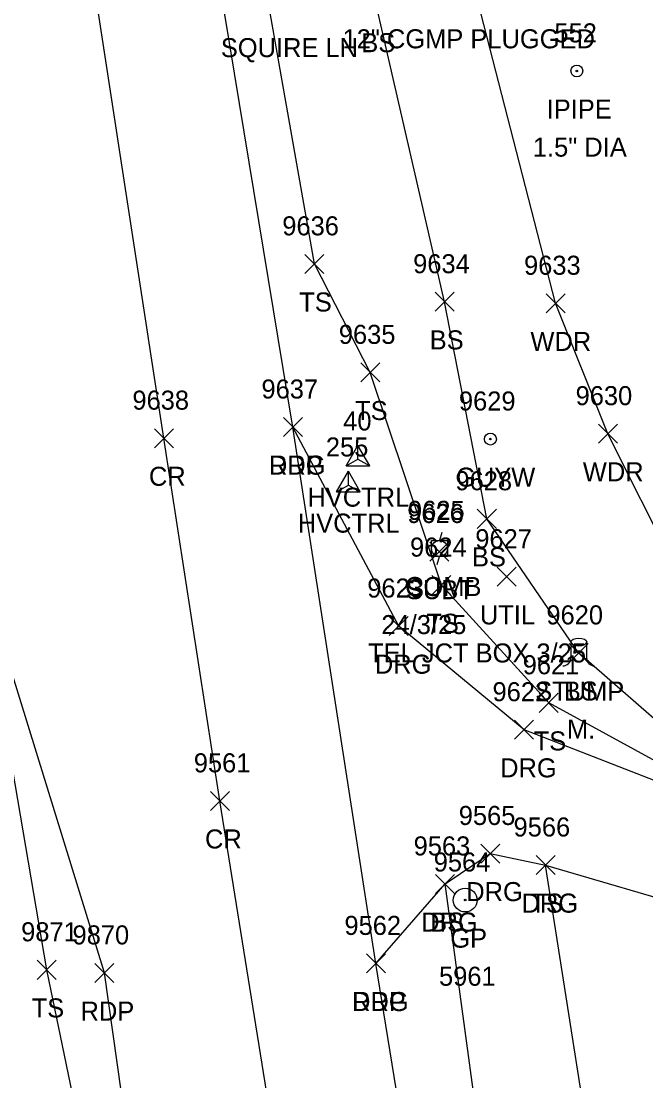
# Model space of a CAD drawing. Extents: x 1439173 to 1457902, y 641926 to 659889.
# Drawn here: x 1448206.5 to 1448272.1, y 646731.6 to 646843 of the extents above; entities that cross this region are included whole.
import ezdxf

# ---------------------------------------------------------------- set-up
doc = ezdxf.new("R2010")
doc.units = 0
for name, color, linetype in [('C_A', 7, 'Continuous'), ('C_I', 7, 'Continuous'), ('CPSM', 7, 'Continuous'), ('D_C', 7, 'Continuous'), ('L_A', 7, 'Continuous'), ('L_C', 7, 'Continuous'), ('L_I', 7, 'Continuous'), ('L_TIC', 7, 'Continuous'), ('LAWA', 7, 'Continuous'), ('LELB', 7, 'Continuous'), ('LTS', 7, 'Continuous'), ('M_A', 7, 'Continuous'), ('M_C', 7, 'Continuous'), ('M_I', 7, 'Continuous'), ('MPIP', 7, 'Continuous'), ('P_A', 7, 'Continuous'), ('P_I', 7, 'Continuous'), ('P_TIC', 7, 'Continuous'), ('PET', 7, 'Continuous'), ('PRC', 7, 'Continuous'), ('R_A', 7, 'Continuous'), ('R_C', 7, 'Continuous'), ('R_I', 7, 'Continuous'), ('R_TIC', 7, 'Continuous'), ('RDG', 7, 'Continuous'), ('RGP', 7, 'Continuous'), ('S_C', 7, 'Continuous'), ('U_A', 7, 'Continuous'), ('U_C', 7, 'Continuous'), ('U_I', 7, 'Continuous'), ('U_TIC', 7, 'Continuous'), ('UDEFAULT', 7, 'Continuous'), ('UP', 7, 'Continuous'), ('UPGW', 7, 'Continuous')]:
    doc.layers.add(name, color=color, linetype=linetype)

msp = doc.modelspace()

# ---------------------------------------------------------------- linework, layer by layer
at = {"layer": 'CPSM'}
for p, q in [((1448240.62, 646796.24), (1448241.87, 646798.4)), ((1448243.12, 646796.24), (1448241.87, 646798.4)), ((1448241.87, 646796.96), (1448241.87, 646798.4)), ((1448240.62, 646796.24), (1448241.87, 646796.96)), ((1448241.87, 646796.96), (1448241.87, 646796.96)), ((1448241.87, 646796.96), (1448243.12, 646796.24)), ((1448239.61, 646793.51), (1448240.86, 646795.67)), ((1448240.62, 646796.24), (1448243.12, 646796.24)), ((1448242.11, 646793.51), (1448240.86, 646795.67)), ((1448240.86, 646794.23), (1448240.86, 646795.67)), ((1448239.61, 646793.51), (1448240.86, 646794.23)), ((1448240.86, 646794.23), (1448240.86, 646794.23)), ((1448240.86, 646794.23), (1448242.11, 646793.51)), ((1448239.61, 646793.51), (1448242.11, 646793.51))]:
    msp.add_line(p, q, dxfattribs=at)
at = {"layer": 'L_TIC'}
for points in [[(1448236.29, 646816.46), (1448238.29, 646818.46)], [(1448238.29, 646816.46), (1448236.29, 646818.46)], [(1448249.97, 646812.48), (1448251.97, 646814.48)], [(1448251.97, 646812.48), (1448249.97, 646814.48)], [(1448261.63, 646812.32), (1448263.63, 646814.32)], [(1448263.63, 646812.32), (1448261.63, 646814.32)], [(1448242.16, 646805.06), (1448244.16, 646807.06)], [(1448244.16, 646805.06), (1448242.16, 646807.06)], [(1448267.14, 646798.62), (1448269.14, 646800.62)], [(1448269.14, 646798.62), (1448267.14, 646800.62)], [(1448254.41, 646789.68), (1448256.41, 646791.68)], [(1448256.41, 646789.68), (1448254.41, 646791.68)], [(1448249.64, 646782.71), (1448251.64, 646784.71)], [(1448251.64, 646782.71), (1448249.64, 646784.71)], [(1448264.06, 646775.59), (1448266.06, 646777.59)], [(1448266.06, 646775.59), (1448264.06, 646777.59)], [(1448260.92, 646770.35), (1448262.92, 646772.35)], [(1448262.92, 646770.35), (1448260.92, 646772.35)], [(1448260.58, 646753.31), (1448262.58, 646755.31)], [(1448262.58, 646753.31), (1448260.58, 646755.31)], [(1448250.02, 646751.32), (1448252.02, 646753.32)], [(1448252.02, 646751.32), (1448250.02, 646753.32)], [(1448208.17, 646742.3), (1448210.17, 646744.3)], [(1448210.17, 646742.3), (1448208.17, 646744.3)]]:
    msp.add_lwpolyline(points, dxfattribs=at)
at = {"layer": 'LAWA'}
msp.add_lwpolyline([(1448339.89, 646844.92), (1448320.73, 646824.25), (1448303.84, 646805.93), (1448275.1, 646785.75), (1448268.14, 646799.62), (1448262.63, 646813.32), (1448252.89, 646851.23), (1448275.91, 646859.54), (1448302.67, 646865.98), (1448312.29, 646860.75), (1448323.5, 646861.84), (1448339.6, 646861.16)], dxfattribs=at)
at = {"layer": 'LELB'}
for points in [[(1448221.02, 646679.97), (1448216.65, 646707.27), (1448209.17, 646743.3), (1448202.24, 646783.83), (1448197.14, 646815.73), (1448192.88, 646849.23), (1448188.79, 646883.91), (1448185.57, 646916.7), (1448180.61, 646928.95), (1448176.05, 646935.8), (1448168.91, 646942.17), (1448163.03, 646939.76)], [(1448286.4, 646757.98), (1448261.92, 646771.35), (1448250.64, 646783.71), (1448243.16, 646806.06), (1448237.29, 646817.46), (1448231.43, 646850.8), (1448233.55, 646856.11)], [(1448286.4, 646757.98), (1448265.06, 646776.59), (1448255.41, 646790.68), (1448250.97, 646813.48), (1448243.78, 646844.7), (1448246.32, 646850.31), (1448252.89, 646851.23)], [(1448318.74, 646292.21), (1448316.52, 646298.57), (1448314.96, 646309.84), (1448311.96, 646334.67), (1448308.77, 646355.56), (1448304.36, 646383.09), (1448300.44, 646410.91), (1448294.85, 646448.68), (1448293.89, 646457.32), (1448293.83, 646460.88), (1448290.31, 646478.07), (1448284.75, 646509.86), (1448279.41, 646543.51), (1448274.67, 646580.58), (1448274.88, 646608.07), (1448272.28, 646641.3), (1448269.27, 646674.15), (1448268, 646713.45), (1448261.58, 646754.31)], [(1448301.58, 646507.94), (1448301.83, 646505.93), (1448300.84, 646506.04), (1448298.73, 646516.23), (1448300.58, 646516.66), (1448296.94, 646526.82), (1448285.25, 646550.8), (1448284.84, 646572.85), (1448274.67, 646580.58), (1448269.38, 646609.39), (1448264.85, 646639.41), (1448260.53, 646672.32), (1448256.24, 646713.95), (1448251.02, 646752.32)]]:
    msp.add_lwpolyline(points, dxfattribs=at)
at = {"layer": 'LTS'}
for p, q in [((1448264.23, 646777.73), (1448264.23, 646776.07)), ((1448265.9, 646777.57), (1448265.9, 646777.73)), ((1448265.9, 646777.73), (1448265.9, 646776.07)), ((1448265.07, 646776.59), (1448265.07, 646776.59)), ((1448265.07, 646776.59), (1448265.07, 646776.59)), ((1448265.07, 646776.57), (1448265.07, 646776.57))]:
    msp.add_line(p, q, dxfattribs=at)
msp.add_circle((1448265.07, 646776.59), 0.0833, dxfattribs=at)
for centre, start, end in [((1448263.4, 646776.07), 270, 360), ((1448266.73, 646776.07), 180, 270)]:
    msp.add_arc(centre, 0.833, start, end, dxfattribs=at)
msp.add_ellipse((1448265.07, 646777.73), major_axis=(-0.833, 0), ratio=0.5, dxfattribs=at)
at = {"layer": 'MPIP'}
for radius in [0.625, 0.0833]:
    msp.add_circle((1448264.87, 646837.73), radius, dxfattribs=at)
at = {"layer": 'P_TIC'}
for points in [[(1448234.04, 646799.32), (1448236.04, 646801.32)], [(1448236.04, 646799.32), (1448234.04, 646801.32)], [(1448220.48, 646798.15), (1448222.48, 646800.15)], [(1448222.48, 646798.15), (1448220.48, 646800.15)], [(1448226.36, 646760.05), (1448228.36, 646762.05)], [(1448228.36, 646760.05), (1448226.36, 646762.05)], [(1448242.76, 646742.97), (1448244.76, 646744.97)], [(1448244.76, 646742.97), (1448242.76, 646744.97)], [(1448214.23, 646741.97), (1448216.23, 646743.97)], [(1448216.23, 646741.97), (1448214.23, 646743.97)]]:
    msp.add_lwpolyline(points, dxfattribs=at)
at = {"layer": 'PET'}
for points in [[(1448246.46, 646550.34), (1448240.19, 646586.21), (1448237.44, 646603.85), (1448232.82, 646631.59), (1448226.85, 646667.5), (1448220.22, 646707.78), (1448215.23, 646742.97), (1448202.82, 646783.14), (1448203.37, 646818.93), (1448198.76, 646850.24), (1448193.44, 646884.14), (1448187.94, 646917.18), (1448185.3, 646933.85), (1448181.56, 646957.89), (1448177.35, 646983.4)], [(1448276.96, 646543.22), (1448270.54, 646579.93), (1448265.59, 646610.13), (1448260.88, 646638.63), (1448255.41, 646671.17), (1448248.66, 646713.73), (1448243.76, 646743.97), (1448235.04, 646800.32), (1448226.34, 646853.04), (1448221.22, 646886.82), (1448214.61, 646928.36), (1448210.31, 646953.97), (1448206.09, 646983.02)]]:
    msp.add_lwpolyline(points, dxfattribs=at)
at = {"layer": 'PRC'}
msp.add_lwpolyline([(1448260.65, 646552.87), (1448253.95, 646593.27), (1448247.21, 646633.9), (1448241.99, 646670.3), (1448235.28, 646711.83), (1448227.36, 646761.05), (1448221.48, 646799.15), (1448208.45, 646883.94), (1448200.39, 646928.86), (1448192.53, 646980.53), (1448184.46, 647032.21), (1448180.05, 647061.28), (1448176.23, 647087.3), (1448169.96, 647123.71), (1448163.11, 647173.92), (1448157.07, 647210.64), (1448152.13, 647238.94), (1448147.96, 647264.25), (1448141.66, 647302.84), (1448134.08, 647349.96), (1448129.97, 647375), (1448122.13, 647423.97), (1448115.84, 647462.16), (1448107.04, 647514.44)], dxfattribs=at)
at = {"layer": 'R_TIC'}
for points in [[(1448234.04, 646799.32), (1448236.04, 646801.32)], [(1448236.04, 646799.32), (1448234.04, 646801.32)], [(1448245.16, 646778.41), (1448247.16, 646780.41)], [(1448247.16, 646778.41), (1448245.16, 646780.41)], [(1448258.32, 646767.52), (1448260.32, 646769.52)], [(1448260.32, 646767.52), (1448258.32, 646769.52)], [(1448254.77, 646754.52), (1448256.77, 646756.52)], [(1448256.77, 646754.52), (1448254.77, 646756.52)], [(1448260.58, 646753.31), (1448262.58, 646755.31)], [(1448262.58, 646753.31), (1448260.58, 646755.31)], [(1448250.02, 646751.32), (1448252.02, 646753.32)], [(1448252.02, 646751.32), (1448250.02, 646753.32)], [(1448242.76, 646742.97), (1448244.76, 646744.97)], [(1448244.76, 646742.97), (1448242.76, 646744.97)]]:
    msp.add_lwpolyline(points, dxfattribs=at)
at = {"layer": 'RDG'}
msp.add_lwpolyline([(1448243.76, 646743.97), (1448251.02, 646752.32), (1448255.77, 646755.52), (1448261.58, 646754.31), (1448277.88, 646749.55), (1448298.63, 646742.52), (1448334.84, 646725.28), (1448349.93, 646713.19), (1448356.27, 646697.5), (1448358.51, 646685.97), (1448360.39, 646682.15), (1448361.75, 646666.18), (1448382.59, 646673.46), (1448377.44, 646696.2), (1448369.9, 646720.52), (1448355.51, 646729.31), (1448322.36, 646743.86), (1448293.59, 646755.1), (1448286.4, 646757.98), (1448259.32, 646768.52), (1448246.16, 646779.41), (1448235.04, 646800.32)], dxfattribs=at)
at = {"layer": 'RGP'}
msp.add_line((1448253.14, 646750.63), (1448253.14, 646750.63), dxfattribs=at)
for radius in [1.25, 0.0833]:
    msp.add_circle((1448253.14, 646750.63), radius, dxfattribs=at)
at = {"layer": 'U_TIC'}
for points in [[(1448249.42, 646786.24), (1448251.42, 646788.24)], [(1448251.42, 646786.24), (1448249.42, 646788.24)]]:
    msp.add_lwpolyline(points, dxfattribs=at)
at = {"layer": 'UDEFAULT'}
for points in [[(1448256.51, 646783.59), (1448258.51, 646785.59)], [(1448258.51, 646783.59), (1448256.51, 646785.59)]]:
    msp.add_lwpolyline(points, dxfattribs=at)
at = {"layer": 'UP'}
for p, q in [((1448250.69, 646789.24), (1448250.44, 646788.4)), ((1448249.6, 646786.74), (1448249.6, 646788.4)), ((1448249.6, 646788.4), (1448251.27, 646788.4)), ((1448250.44, 646787.57), (1448250.44, 646787.57)), ((1448251.27, 646788.4), (1448251.27, 646786.74)), ((1448251.27, 646786.74), (1448249.6, 646786.74)), ((1448250.19, 646785.9), (1448250.44, 646786.74))]:
    msp.add_line(p, q, dxfattribs=at)
msp.add_circle((1448250.44, 646787.57), 0.833, dxfattribs=at)
at = {"layer": 'UPGW'}
for radius in [0.625, 0.0833]:
    msp.add_circle((1448255.79, 646799.06), radius, dxfattribs=at)

# ---------------------------------------------------------------- texts
at = {"layer": 'C_A'}
for p in [(1448236.56, 646791.96), (1448235.55, 646789.23)]:
    msp.add_text('HVCTRL', height=2, dxfattribs=at).set_placement(p)
at = {"layer": 'C_I'}
for s, p in [('40', (1448240.32, 646799.96)), ('255', (1448238.5, 646797.23))]:
    msp.add_text(s, height=2, dxfattribs=at).set_placement(p)
at = {"layer": 'D_C'}
msp.add_text('12" CGMP PLUGGED', height=2, dxfattribs=at).set_placement((1448240.25, 646840.11))
at = {"layer": 'L_A'}
for s, p in [('BS', (1448242.22, 646839.7)), ('TS', (1448235.7, 646812.46)), ('BS', (1448249.41, 646808.48)), ('WDR', (1448259.99, 646808.32)), ('TS', (1448241.57, 646801.06)), ('WDR', (1448265.5, 646794.62)), ('BS', (1448253.85, 646785.68)), ('TS', (1448249.05, 646778.71)), ('STUMP', (1448260.49, 646771.59)), ('BS', (1448263.5, 646771.59)), ('TS', (1448260.33, 646766.35)), ('TS', (1448259.99, 646749.31)), ('BS', (1448249.46, 646747.32)), ('TS', (1448207.58, 646738.3))]:
    msp.add_text(s, height=2, dxfattribs=at).set_placement(p)
at = {"layer": 'L_C'}
msp.add_text('M.', height=2, dxfattribs=at).set_placement((1448263.83, 646767.59))
at = {"layer": 'L_I'}
for s, p in [('9636', (1448233.92, 646820.46)), ('9634', (1448247.67, 646816.48)), ('9633', (1448259.32, 646816.32)), ('9635', (1448239.86, 646809.06)), ('9630', (1448264.74, 646802.62)), ('9628', (1448252.11, 646793.68)), ('9624', (1448247.34, 646786.71)), ('9620', (1448261.67, 646779.59)), ('9620', (1448261.67, 646779.59)), ('9621', (1448259.18, 646774.35)), ('9566', (1448258.22, 646757.31)), ('9563', (1448247.72, 646755.32)), ('9871', (1448206.48, 646746.3))]:
    msp.add_text(s, height=2, dxfattribs=at).set_placement(p)
at = {"layer": 'M_A'}
msp.add_text('IPIPE', height=2, dxfattribs=at).set_placement((1448261.7, 646832.73))
at = {"layer": 'M_C'}
msp.add_text('1.5" DIA', height=2, dxfattribs=at).set_placement((1448260.25, 646828.73))
at = {"layer": 'M_I'}
msp.add_text('552', height=2, dxfattribs=at).set_placement((1448262.51, 646840.73))
at = {"layer": 'P_A'}
for s, p in [('RDP', (1448232.52, 646795.32)), ('CR', (1448219.91, 646794.15)), ('CR', (1448225.8, 646756.05)), ('RDP', (1448241.25, 646738.97)), ('RDP', (1448212.72, 646737.97))]:
    msp.add_text(s, height=2, dxfattribs=at).set_placement(p)
at = {"layer": 'P_I'}
for s, p in [('9637', (1448231.73, 646803.32)), ('9638', (1448218.17, 646802.15)), ('9561', (1448224.62, 646764.05)), ('9562', (1448240.45, 646746.97)), ('9870', (1448211.88, 646745.97))]:
    msp.add_text(s, height=2, dxfattribs=at).set_placement(p)
at = {"layer": 'R_A'}
for s, p in [('DRG', (1448232.52, 646795.32)), ('DRG', (1448243.65, 646774.41)), ('DRG', (1448256.81, 646763.52)), ('DRG', (1448253.25, 646750.52)), ('DRG', (1448259.07, 646749.31)), ('DRG', (1448248.51, 646747.32)), ('GP', (1448251.57, 646745.63)), ('DRG', (1448241.25, 646738.97))]:
    msp.add_text(s, height=2, dxfattribs=at).set_placement(p)
at = {"layer": 'R_C'}
msp.add_text('5961', height=2, dxfattribs=at).set_placement((1448250.39, 646741.63))
at = {"layer": 'R_I'}
for s, p in [('9637', (1448231.73, 646803.32)), ('9623', (1448242.85, 646782.41)), ('9622', (1448256.01, 646771.52)), ('9565', (1448252.46, 646758.52)), ('9566', (1448258.22, 646757.31)), ('9563', (1448247.72, 646755.32)), ('9564', (1448249.83, 646753.63)), ('9562', (1448240.45, 646746.97))]:
    msp.add_text(s, height=2, dxfattribs=at).set_placement(p)
at = {"layer": 'S_C'}
msp.add_text('SQUIRE LN', height=2, dxfattribs=at).set_placement((1448227.46, 646839.18))
at = {"layer": 'U_A'}
for s, p in [('GUYW', (1448252.18, 646794.06)), ('COMB', (1448246.82, 646782.57)), ('SUBT', (1448246.91, 646782.24)), ('UTIL', (1448254.68, 646779.59))]:
    msp.add_text(s, height=2, dxfattribs=at).set_placement(p)
at = {"layer": 'U_C'}
for s, p in [('24/3/25', (1448244.33, 646778.57)), ('TEL JCT BOX 3/25', (1448242.94, 646775.59))]:
    msp.add_text(s, height=2, dxfattribs=at).set_placement(p)
at = {"layer": 'U_I'}
for s, p in [('9629', (1448252.48, 646802.06)), ('9626', (1448247.05, 646790.24)), ('9625', (1448247.13, 646790.57)), ('9627', (1448254.2, 646787.59))]:
    msp.add_text(s, height=2, dxfattribs=at).set_placement(p)

doc.saveas('drawing.dxf')
